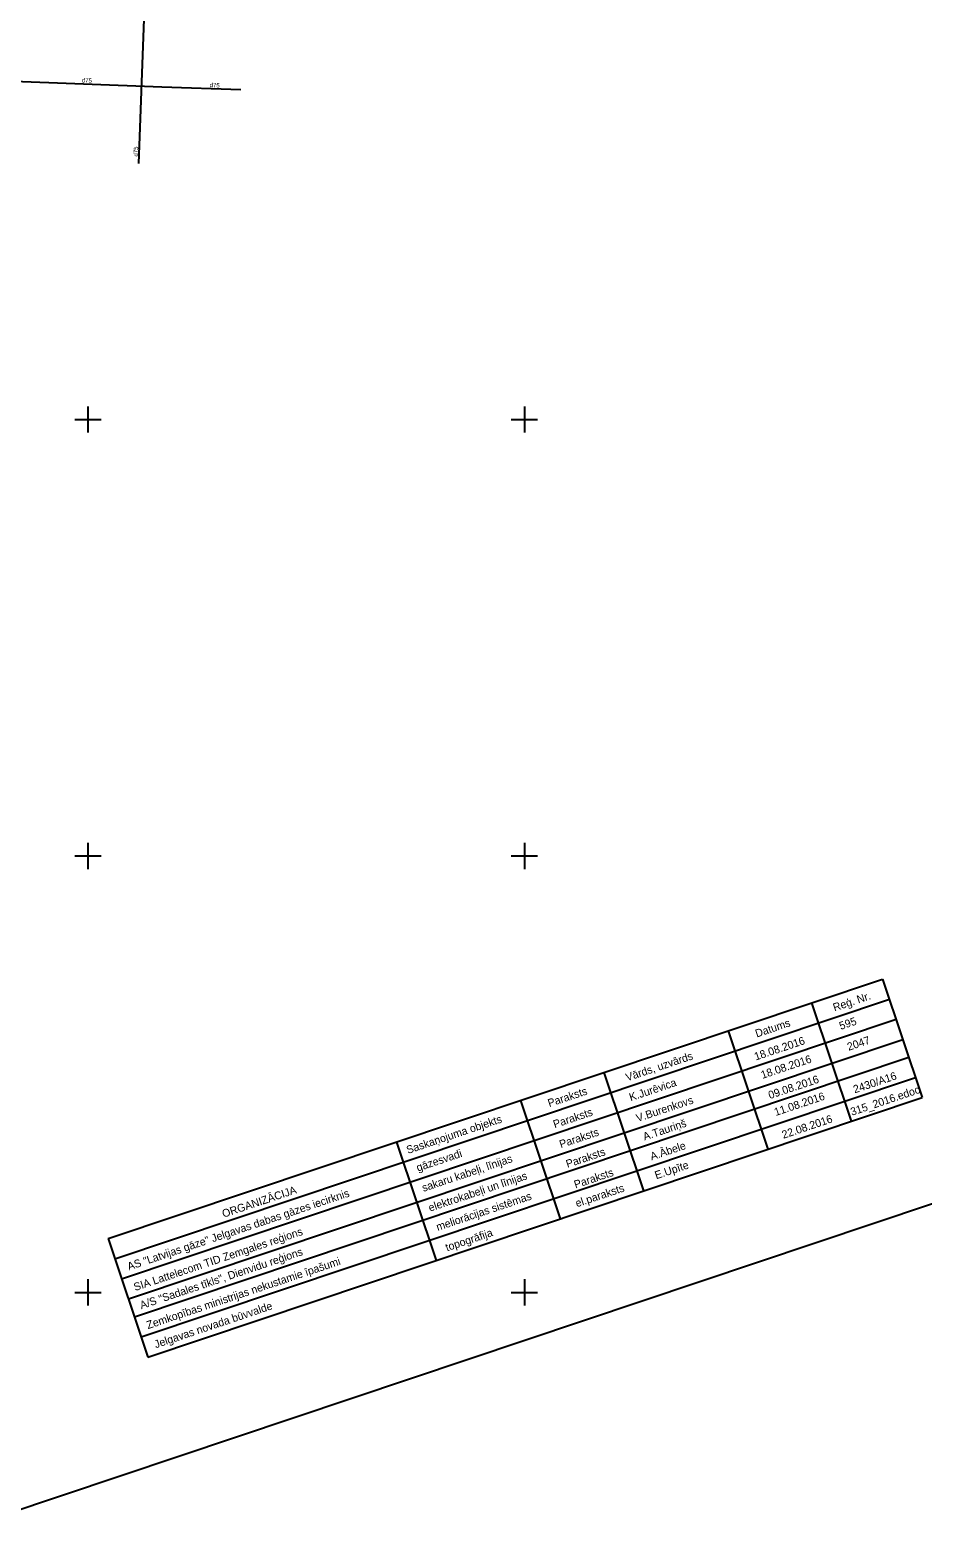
# Model space of a CAD drawing. Extents: x 469981 to 472086, y 246785 to 247785.
# Drawn here: x 470343.4 to 470445.6, y 246871.9 to 247044.6 of the extents above; entities that cross this region are included whole.
import ezdxf

# ---------------------------------------------------------------- set-up
doc = ezdxf.new("R2010")
doc.units = 0
for name, color, linetype in [('DREN_VADP_KLKT_####_#', 7, 'Continuous'), ('DREN_VADP_KLKT_TKST_#', 7, 'Continuous'), ('GEOD_ELEM_####_####_#', 7, 'Continuous'), ('RAMI_PLAN_####_TKST_#', 7, 'Continuous'), ('RELJ_NOGA_####_####_#', 7, 'Continuous'), ('RELJ_NOGL_####_####_#', 7, 'Continuous')]:
    doc.layers.add(name, color=color, linetype=linetype)

msp = doc.modelspace()

# ---------------------------------------------------------------- linework, layer by layer
at = {"layer": 'DREN_VADP_KLKT_####_#'}
for points in [[(470355.84, 247029.32), (470356.44, 247045.88), (470357.29, 247069.47), (470322.27, 247033.82), (470311.43, 247022.79), (470278.3, 246989.07), (470265.46, 246976), (470248.26, 246964.75), (470217.93, 246944.91)], [(470313.86, 247017.9), (470324.3, 247026.07), (470339.61, 247038.06), (470340.53, 247038.79), (470358.46, 247038.13), (470367.52, 247037.8)]]:
    msp.add_lwpolyline(points, dxfattribs=at)
at = {"layer": 'GEOD_ELEM_####_####_#'}
for p, q in [((470350, 247001.5), (470350, 247000)), ((470400, 247001.5), (470400, 247000)), ((470348.5, 247000), (470350, 247000)), ((470350, 247000), (470350, 246998.5)), ((470350, 247000), (470351.5, 247000)), ((470398.5, 247000), (470400, 247000)), ((470400, 247000), (470400, 246998.5)), ((470400, 247000), (470401.5, 247000)), ((470350, 246951.5), (470350, 246950)), ((470400, 246951.5), (470400, 246950)), ((470348.5, 246950), (470350, 246950)), ((470350, 246950), (470350, 246948.5)), ((470350, 246950), (470351.5, 246950)), ((470398.5, 246950), (470400, 246950)), ((470400, 246950), (470400, 246948.5)), ((470400, 246950), (470401.5, 246950)), ((470350, 246901.5), (470350, 246900)), ((470400, 246901.5), (470400, 246900)), ((470348.5, 246900), (470350, 246900)), ((470350, 246900), (470350, 246898.5)), ((470350, 246900), (470351.5, 246900)), ((470398.5, 246900), (470400, 246900)), ((470400, 246900), (470400, 246898.5)), ((470400, 246900), (470401.5, 246900))]:
    msp.add_line(p, q, dxfattribs=at)
at = {"layer": 'RAMI_PLAN_####_TKST_#'}
for p, q in [((470352.32, 246906.16), (470441.04, 246935.9)), ((470441.04, 246935.9), (470445.58, 246922.33)), ((470353.09, 246903.86), (470441.81, 246933.59)), ((470432.88, 246933.17), (470437.43, 246919.6)), ((470353.86, 246901.55), (470442.58, 246931.29)), ((470354.64, 246899.25), (470443.35, 246928.99)), ((470423.34, 246929.97), (470427.89, 246916.4)), ((470355.32, 246897.2), (470444.04, 246926.94)), ((470409.1, 246925.19), (470413.65, 246911.63)), ((470356.1, 246894.9), (470444.81, 246924.63)), ((470356.87, 246892.59), (470445.58, 246922.33)), ((470399.54, 246921.99), (470404.09, 246908.42)), ((470385.34, 246917.23), (470389.89, 246903.66)), ((470352.32, 246906.16), (470356.87, 246892.59))]:
    msp.add_line(p, q, dxfattribs=at)
msp.add_lwpolyline([(470585.96, 246956.81), (470074.9, 246785.5), (469981.15, 247065.2), (470492.2, 247236.51)], close=True, dxfattribs=at)
at = {"layer": 'RELJ_NOGA_####_####_#'}
msp.add_spline([(470120.85, 246890.77), (470123.59, 246892.47), (470150.35, 246909.18), (470171.26, 246922.11), (470191.15, 246935.73), (470210.2, 246948.51), (470224.2, 246958.07), (470243.11, 246970.41), (470266.52, 246987.91), (470280.54, 247001.25), (470299.82, 247020.38), (470317.59, 247038.54), (470334.88, 247055.83), (470351.43, 247073.19), (470366.15, 247085.97)], degree=3, dxfattribs=at)
at = {"layer": 'RELJ_NOGL_####_####_#'}
msp.add_spline([(470122.05, 246889.92), (470124.65, 246891.61), (470151.26, 246908.03), (470171.62, 246921.5), (470191.87, 246934.82), (470224.88, 246957.28), (470243.43, 246969.86), (470267.18, 246986.98), (470282.02, 246999.84), (470300.68, 247018.66), (470318.83, 247036.85), (470336.23, 247054.12), (470352.94, 247071.37), (470367.14, 247084.45)], degree=3, dxfattribs=at)

# ---------------------------------------------------------------- texts
at = {"layer": 'DREN_VADP_KLKT_TKST_#'}
for rotation, p in [(357.9014, (470349.29, 247038.62)), (357.9016, (470363.93, 247038.08)), (87.9283, (470355.72, 247030.12))]:
    msp.add_text('d75', height=0.5, rotation=rotation, dxfattribs=at).set_placement(p)
at = {"layer": 'RAMI_PLAN_####_TKST_#'}
for s, p in [('Reģ. Nr.', (470435.53, 246932.19)), ('Datums', (470426.62, 246929.2)), ('595', (470436.24, 246930.07)), ('18.08.2016', (470426.51, 246926.56)), ('2047', (470437.15, 246927.68)), ('Vārds, uzvārds', (470411.78, 246924.18)), ('18.08.2016', (470427.27, 246924.46)), (' 2430/A16', (470437.53, 246922.7)), ('Paraksts', (470402.85, 246921.22)), ('K.Jurēvica', (470412.18, 246921.9)), ('09.08.2016', (470428.12, 246922.14)), ('315_2016.edoc', (470437.53, 246920.23)), ('V.Burenkovs', (470412.97, 246919.51)), ('11.08.2016', (470428.79, 246920.2)), ('Saskaņojuma objekts', (470386.66, 246915.86)), ('Paraksts', (470403.47, 246918.81)), ('A.Tauriņš', (470413.76, 246917.39)), ('22.08.2016', (470429.67, 246917.6)), ('Paraksts', (470404.18, 246916.52)), ('gāzesvadi', (470387.8, 246913.84)), ('A.Ābele', (470414.58, 246915.12)), ('sakaru kabeļi, līnijas', (470388.44, 246911.52)), ('Paraksts', (470404.93, 246914.26)), ('E.Upīte', (470415.11, 246912.96)), ('elektrokabeļi un līnijas', (470389.18, 246909.24)), ('Paraksts', (470405.86, 246911.9)), ('AS "Latvijas gāze" Jelgavas dabas gāzes iecirknis', (470354.68, 246902.51)), ('ORGANIZĀCIJA', (470365.54, 246908.55)), ('meliorācijas sistēmas', (470390.07, 246907.04)), ('el.paraksts', (470406.02, 246909.75)), ('SIA Lattelecom TID Zemgales reģions', (470355.41, 246900.15)), ('topogrāfija', (470391.13, 246904.7)), ('A/S "Sadales tīkls", Dienvidu reģions', (470356.12, 246898.07)), ('Zemkopības ministrijas nekustamie īpašumi', (470356.88, 246895.79)), ('Jelgavas novada būvvalde', (470357.77, 246893.59))]:
    msp.add_text(s, height=0.9, rotation=18.5312, dxfattribs=at).set_placement(p)

doc.saveas('drawing.dxf')
